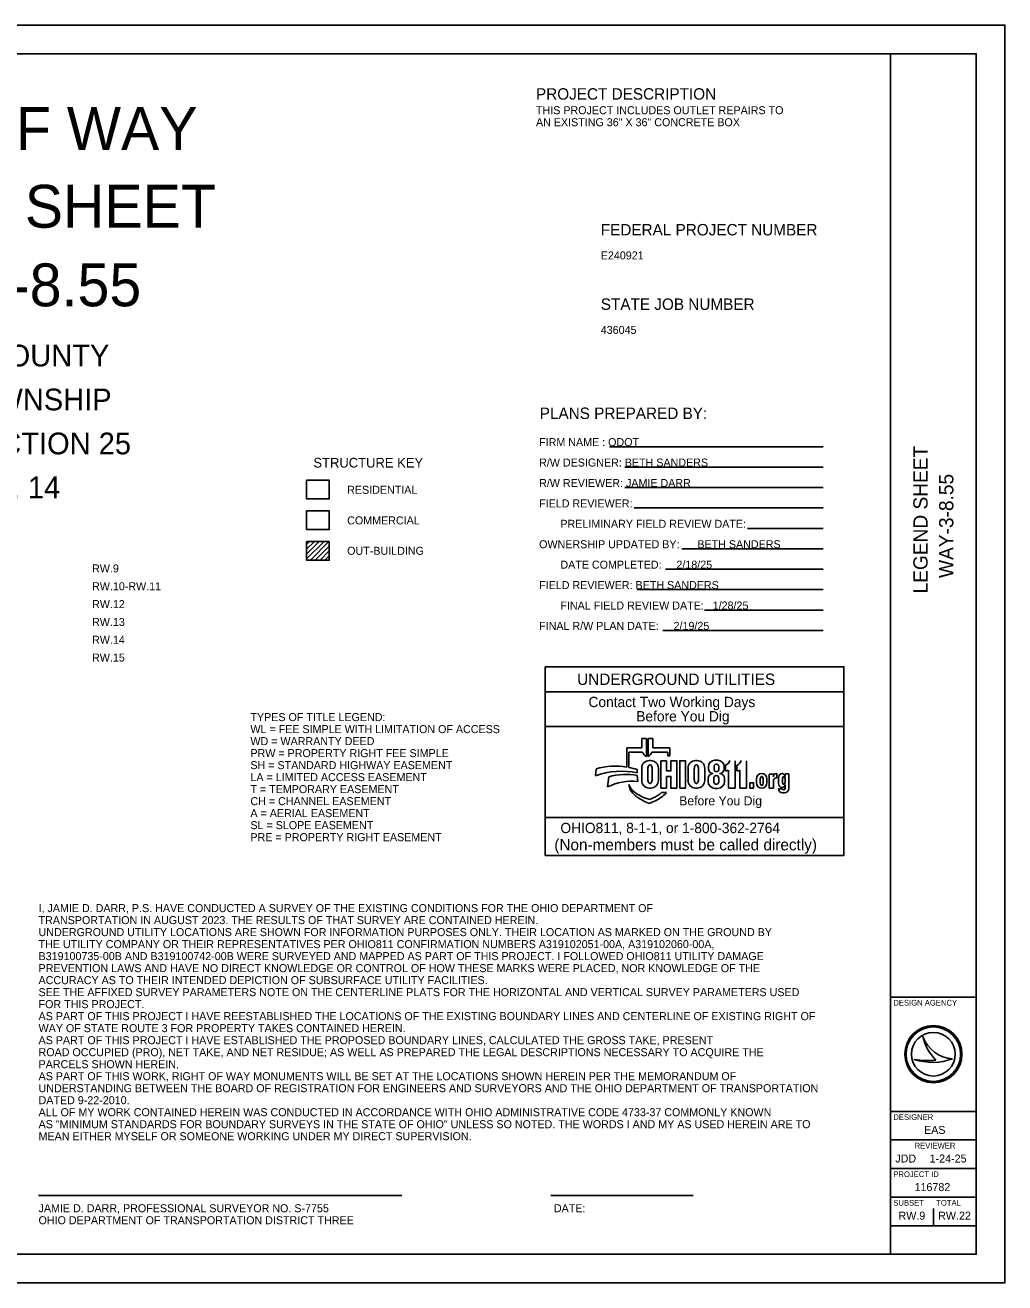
# Model space of a CAD drawing. Extents: x 0 to 34, y 0 to 22.
# Drawn here: x 16.87 to 34, y 0 to 22 of the extents above; entities that cross this region are included whole.
import ezdxf

# ---------------------------------------------------------------- set-up
doc = ezdxf.new("R2010")
doc.units = 0
for name, color, linetype in [('Default', 7, 'Continuous'), ('SC_Shading1', 7, 'Continuous'), ('SH_Border', 7, 'Continuous'), ('SH_Cut_Line', 7, 'Continuous'), ('SH_Data', 7, 'Continuous'), ('SH_Text', 7, 'Continuous')]:
    doc.layers.add(name, color=color, linetype=linetype)

msp = doc.modelspace()

# ---------------------------------------------------------------- linework, layer by layer
at = {"layer": 'Default'}
for p, q in [((17.102, 1.525), (23.455, 1.525)), ((26.062, 1.525), (28.549, 1.525))]:
    msp.add_line(p, q, dxfattribs=at)
at = {"layer": 'SC_Shading1'}
msp.add_lwpolyline([(21.79, 13.177), (22.187, 13.177), (22.187, 13.502), (21.79, 13.502)], close=True, dxfattribs=at)
at = {"layer": 'SH_Border'}
for p, q in [((32, 0.5), (32, 21.5)), ((32, 5), (33.5, 5)), ((32, 3), (33.5, 3)), ((32, 2.5), (33.5, 2.5)), ((32, 2), (33.5, 2)), ((32, 1.5), (33.5, 1.5)), ((32, 1), (33.5, 1))]:
    msp.add_line(p, q, dxfattribs=at)
msp.add_lwpolyline([(1.5, 21.5), (33.5, 21.5), (33.5, 0.5), (1.5, 0.5)], close=True, dxfattribs=at)
at = {"layer": 'SH_Cut_Line'}
msp.add_lwpolyline([(0, 0), (34, 0), (34, 22), (0, 22)], close=True, dxfattribs=at)
at = {"layer": 'SH_Data'}
for p, q in [((27.731, 9.524), (27.651, 9.524)), ((27.651, 9.524), (27.651, 9.357)), ((27.731, 9.207), (27.731, 9.524)), ((27.842, 9.524), (27.762, 9.524)), ((27.762, 9.524), (27.762, 9.207)), ((27.842, 9.357), (27.842, 9.524)), ((27.651, 9.357), (27.388, 9.357)), ((27.388, 9.357), (27.388, 9.023)), ((27.425, 9.016), (27.425, 9.28)), ((27.425, 9.28), (27.666, 9.28)), ((27.826, 9.28), (28.105, 9.28)), ((28.14, 9.357), (27.842, 9.357)), ((28.105, 9.28), (28.105, 9.217)), ((28.14, 9.217), (28.14, 9.357)), ((27.807, 9.136), (27.783, 9.136)), ((28.085, 9.134), (27.984, 9.134)), ((27.984, 9.134), (27.984, 8.656)), ((28.105, 9.217), (28.14, 9.217)), ((28.618, 9.136), (28.593, 9.136)), ((28.816, 9.028), (28.816, 8.992)), ((28.915, 8.975), (28.915, 9.034)), ((28.979, 9.142), (28.93, 9.142)), ((28.996, 9.034), (28.996, 8.975)), ((29.093, 8.992), (29.093, 9.028)), ((29.116, 8.954), (29.116, 9.056)), ((29.283, 9.134), (29.283, 8.656)), ((29.316, 8.954), (29.316, 9.056)), ((29.483, 9.134), (29.483, 8.656)), ((26.853, 8.988), (26.839, 8.872)), ((27.073, 8.853), (27.051, 8.674)), ((27.572, 8.921), (27.572, 8.979)), ((27.582, 8.77), (27.572, 8.876)), ((27.649, 9.002), (27.649, 8.79)), ((27.758, 8.807), (27.758, 8.99)), ((27.832, 8.99), (27.832, 8.807)), ((27.941, 8.79), (27.941, 9.002)), ((28.085, 8.656), (28.085, 8.859)), ((28.46, 9.002), (28.46, 8.79)), ((28.569, 8.807), (28.569, 8.99)), ((28.643, 8.99), (28.643, 8.807)), ((28.752, 8.79), (28.752, 9.002)), ((28.811, 8.822), (28.811, 8.771)), ((28.912, 8.762), (28.912, 8.823)), ((28.997, 8.823), (28.997, 8.762)), ((29.099, 8.771), (29.099, 8.822)), ((29.165, 8.656), (29.165, 8.968)), ((29.365, 8.656), (29.365, 8.968)), ((29.657, 8.747), (29.657, 8.815)), ((29.724, 8.746), (29.724, 8.815)), ((29.772, 8.815), (29.772, 8.746)), ((29.839, 8.815), (29.839, 8.747)), ((29.952, 8.9), (29.879, 8.9)), ((29.879, 8.9), (29.879, 8.656)), ((29.952, 8.853), (29.952, 8.9)), ((30.001, 8.833), (30.013, 8.833)), ((30.013, 8.908), (30.007, 8.908)), ((30.013, 8.833), (30.013, 8.908)), ((30.041, 8.735), (30.041, 8.839)), ((30.113, 8.749), (30.113, 8.825)), ((30.156, 8.855), (30.156, 8.901)), ((30.156, 8.901), (30.221, 8.901)), ((30.156, 8.825), (30.156, 8.749)), ((30.221, 8.901), (30.221, 8.643)), ((27.424, 8.717), (27.429, 8.69)), ((27.783, 8.656), (27.807, 8.656)), ((27.984, 8.656), (28.085, 8.656)), ((28.593, 8.656), (28.618, 8.656)), ((28.932, 8.65), (28.978, 8.65)), ((29.283, 8.656), (29.165, 8.656)), ((29.483, 8.656), (29.365, 8.656)), ((29.879, 8.656), (29.952, 8.656)), ((29.952, 8.656), (29.952, 8.784)), ((30.041, 8.643), (30.113, 8.643)), ((30.156, 8.643), (30.156, 8.712)), ((27.789, 8.456), (27.701, 8.486)), ((27.725, 8.41), (27.78, 8.385)), ((27.78, 8.385), (27.875, 8.426)), ((27.851, 8.482), (27.789, 8.456)), ((28.083, 8.576), (27.997, 8.576)), ((28.08, 8.574), (28.083, 8.576)), ((30.151, 8.573), (30.111, 8.573)), ((31.187, 7.478), (25.962, 7.478)), ((32.567, 4.31), (32.567, 4.31)), ((32.75, 4), (32.75, 4)), ((32.417, 3.91), (32.417, 3.91)), ((33.087, 3.919), (33.087, 3.919)), ((32.75, 1), (32.75, 1.3))]:
    msp.add_line(p, q, dxfattribs=at)
for points in [[(25.962, 10.778), (31.187, 10.778), (31.187, 10.338), (25.962, 10.338)], [(25.962, 10.338), (31.187, 10.338), (31.187, 9.733), (25.962, 9.733)], [(25.962, 9.733), (31.187, 9.733), (31.187, 8.138), (25.962, 8.138)], [(29.541, 8.746), (29.607, 8.746), (29.607, 8.656), (29.541, 8.656)], [(25.962, 8.138), (31.187, 8.138), (31.187, 7.478), (25.962, 7.478)]]:
    msp.add_lwpolyline(points, close=True, dxfattribs=at)
for points in [[(28.085, 8.859), (28.161, 8.859), (28.161, 8.656), (28.263, 8.656), (28.263, 9.134), (28.161, 9.134), (28.161, 8.954), (28.085, 8.954), (28.085, 9.134)], [(28.314, 8.656), (28.416, 8.656), (28.416, 9.134), (28.314, 9.134), (28.314, 8.656)], [(28.897, 8.909), (28.897, 8.908)], [(29.013, 8.908), (29.013, 8.909)]]:
    msp.add_lwpolyline(points, dxfattribs=at)
for radius in [0.5, 0.477, 0.477, 0.382]:
    msp.add_circle((32.75, 4), radius, dxfattribs=at)
for centre, radius, start, end in [((27.803, 9.335), 0.147, 201.9296, 240.7469), ((27.69, 9.335), 0.147, 299.2531, 338.0704), ((27.196, 7.814), 1.224, 81.0007, 106.3144), ((27.783, 9.002), 0.134, 90, 180), ((27.807, 9.002), 0.134, 0, 90), ((28.593, 9.002), 0.134, 90, 180), ((28.618, 9.002), 0.134, 0, 90), ((28.93, 9.028), 0.114, 90, 180), ((28.979, 9.028), 0.114, 0, 90), ((29.066, 9.178), 0.132, 292.5572, 340.7355), ((29.266, 9.178), 0.132, 292.5572, 340.7355), ((27.291, 7.618), 1.332, 77.8238, 109.8274), ((27.372, 7.801), 1.094, 79.44, 105.8467), ((27.196, 7.814), 1.224, 72.1402, 79.2074), ((28.897, 8.822), 0.0865, 90, 180), ((28.9, 8.992), 0.0837, 180, 268.1442), ((29.01, 8.992), 0.0837, 272.2058, 0), ((29.013, 8.822), 0.0865, 0, 90), ((29.104, 9.086), 0.132, 275.1733, 297.0931), ((29.304, 9.086), 0.132, 275.1733, 297.0931), ((29.752, 8.815), 0.0956, 92.5886, 180), ((29.744, 8.815), 0.0956, 0, 87.4114), ((30.007, 8.853), 0.0548, 90, 180), ((30.001, 8.784), 0.0493, 90, 180), ((30.109, 8.839), 0.0686, 92.6865, 180), ((30.103, 8.855), 0.0524, 0, 86.9262), ((27.479, 7.826), 0.95, 83.8248, 116.8021), ((27.704, 8.824), 0.3, 201.0457, 232.5314), ((27.64, 8.726), 0.214, 189.6817, 216.0884), ((27.84, 8.871), 0.461, 216.0884, 235.7167), ((27.992, 9.2), 0.773, 232.5314, 241.794), ((27.783, 8.79), 0.134, 180, 270), ((27.807, 8.79), 0.134, 270, 0), ((28.593, 8.79), 0.134, 180, 270), ((28.618, 8.79), 0.134, 270, 0), ((28.932, 8.771), 0.121, 180, 270), ((28.978, 8.771), 0.121, 270, 0), ((29.752, 8.747), 0.0956, 180, 267.4114), ((29.744, 8.747), 0.0956, 272.5886, 0), ((30.11, 8.735), 0.0692, 180, 265.7132), ((30.111, 8.643), 0.0699, 180, 270), ((30.109, 8.712), 0.0467, 264.7825, 0), ((30.151, 8.643), 0.0699, 270, 0), ((28.088, 9.236), 0.903, 235.7167, 246.2325), ((27.865, 8.962), 0.504, 241.794, 250.9821), ((27.637, 8.976), 0.538, 293.4582, 312.0712), ((27.637, 8.976), 0.599, 293.4582, 317.8286), ((33.116, 4.498), 0.58, 198.9257, 198.9319), ((33.347, 4.47), 0.796, 191.6379, 191.6421), ((33.116, 4.498), 0.58, 198.9319, 267.1657), ((33.347, 4.47), 0.796, 191.6421, 226.0947), ((32.739, 4.87), 1.013, 251.4576, 290.0832), ((32.648, 5.154), 1.266, 259.4964, 259.4995), ((32.739, 4.87), 1.013, 251.4527, 251.4576), ((32.648, 5.154), 1.266, 259.4995, 276.6672)]:
    msp.add_arc(centre, radius, start, end, dxfattribs=at)
for centre, major_axis, ratio, start_param, end_param in [((27.795, 8.99), (0, 0.0723), 0.514403, 4.712389, 7.853982), ((28.606, 8.99), (0, 0.0723), 0.514403, 4.712389, 7.853982), ((28.956, 9.034), (0.0404, 0), 0.969373, 0, 3.141593), ((27.795, 8.807), (0, 0.0723), 0.514403, 1.570796, 4.712389), ((28.606, 8.807), (0, 0.0723), 0.514403, 1.570796, 4.712389), ((28.954, 8.823), (0, 0.0535), 0.794529, 4.712389, 7.853982), ((28.956, 8.975), (0.0404, 0), 0.818453, 3.141593, 6.283185), ((29.748, 8.815), (0, 0.0434), 0.553236, 4.712389, 7.853982), ((30.134, 8.825), (0, 0.0275), 0.777179, 4.712389, 7.853982), ((28.954, 8.762), (0.0425, 0), 0.959837, 3.141593, 6.283185), ((29.748, 8.746), (0, 0.046), 0.522014, 1.570796, 4.712389), ((30.134, 8.749), (0, 0.0275), 0.777179, 1.570796, 4.712389), ((30.134, 8.643), (0.0214, 0), 0.959012, 3.141593, 6.283185)]:
    msp.add_ellipse(centre, major_axis=major_axis, ratio=ratio, start_param=start_param, end_param=end_param, dxfattribs=at)
at = {"layer": 'SH_Text'}
for p, q in [((27.088, 14.626), (30.825, 14.626)), ((27.352, 14.269), (30.825, 14.269)), ((27.352, 13.912), (30.825, 13.912)), ((27.516, 13.554), (30.825, 13.554)), ((29.497, 13.197), (30.825, 13.197)), ((21.79, 12.966), (21.792, 12.967)), ((21.79, 12.916), (21.842, 12.967)), ((21.79, 12.831), (21.927, 12.967)), ((21.79, 12.746), (22.011, 12.967)), ((21.79, 12.662), (22.096, 12.967)), ((21.855, 12.641), (22.181, 12.967)), ((21.939, 12.641), (22.187, 12.889)), ((22.024, 12.641), (22.187, 12.805)), ((28.352, 12.84), (30.825, 12.84)), ((21.79, 12.646), (21.795, 12.641)), ((22.109, 12.641), (22.187, 12.72)), ((28.067, 12.483), (30.825, 12.483)), ((27.569, 12.126), (30.825, 12.126)), ((28.75, 11.768), (30.825, 11.768)), ((28.021, 11.412), (30.825, 11.412))]:
    msp.add_line(p, q, dxfattribs=at)
for points in [[(21.79, 14.038), (22.187, 14.038), (22.187, 13.712), (21.79, 13.712)], [(21.79, 12.967), (22.187, 12.967), (22.187, 12.641), (21.79, 12.641)]]:
    msp.add_lwpolyline(points, close=True, dxfattribs=at)

# ---------------------------------------------------------------- texts
at = {"layer": 'Default'}
for s, p in [('I, JAMIE D. DARR, P.S. HAVE CONDUCTED A SURVEY OF THE EXISTING CONDITIONS FOR THE OHIO DEPARTMENT OF', (17.102, 6.485)), ('TRANSPORTATION IN AUGUST 2023. THE RESULTS OF THAT SURVEY ARE CONTAINED HEREIN.', (17.102, 6.275)), ('UNDERGROUND UTILITY LOCATIONS ARE SHOWN FOR INFORMATION PURPOSES ONLY. THEIR LOCATION AS MARKED ON THE GROUND BY ', (17.102, 6.065)), ('THE UTILITY COMPANY OR THEIR REPRESENTATIVES PER OHIO811 CONFIRMATION NUMBERS A319102051-00A, A319102060-00A,', (17.102, 5.855)), ('B319100735-00B AND B319100742-00B WERE SURVEYED AND MAPPED AS PART OF THIS PROJECT. I FOLLOWED OHIO811 UTILITY DAMAGE', (17.102, 5.645)), ('PREVENTION LAWS AND HAVE NO DIRECT KNOWLEDGE OR CONTROL OF HOW THESE MARKS WERE PLACED, NOR KNOWLEDGE OF THE ', (17.102, 5.435)), ('ACCURACY AS TO THEIR INTENDED DEPICTION OF SUBSURFACE UTILITY FACILITIES.', (17.102, 5.225)), ('SEE THE AFFIXED SURVEY PARAMETERS NOTE ON THE CENTERLINE PLATS FOR THE HORIZONTAL AND VERTICAL SURVEY PARAMETERS USED ', (17.102, 5.015)), ('FOR THIS PROJECT.', (17.102, 4.805)), ('AS PART OF THIS PROJECT I HAVE REESTABLISHED THE LOCATIONS OF THE EXISTING BOUNDARY LINES AND CENTERLINE OF EXISTING RIGHT OF ', (17.102, 4.595)), ('WAY OF STATE ROUTE 3 FOR PROPERTY TAKES CONTAINED HEREIN.', (17.102, 4.385)), ('AS PART OF THIS PROJECT I HAVE ESTABLISHED THE PROPOSED BOUNDARY LINES, CALCULATED THE GROSS TAKE, PRESENT', (17.102, 4.175)), ('ROAD OCCUPIED (PRO), NET TAKE, AND NET RESIDUE; AS WELL AS PREPARED THE LEGAL DESCRIPTIONS NECESSARY TO ACQUIRE THE', (17.102, 3.965)), ('PARCELS SHOWN HEREIN.', (17.102, 3.755)), ('AS PART OF THIS WORK, RIGHT OF WAY MONUMENTS WILL BE SET AT THE LOCATIONS SHOWN HEREIN PER THE MEMORANDUM OF ', (17.102, 3.545)), ('UNDERSTANDING BETWEEN THE BOARD OF REGISTRATION FOR ENGINEERS AND SURVEYORS AND THE OHIO DEPARTMENT OF TRANSPORTATION ', (17.102, 3.335)), ('DATED 9-22-2010.', (17.102, 3.125)), ('ALL OF MY WORK CONTAINED HEREIN WAS CONDUCTED IN ACCORDANCE WITH OHIO ADMINISTRATIVE CODE 4733-37 COMMONLY KNOWN', (17.102, 2.915)), ('AS "MINIMUM STANDARDS FOR BOUNDARY SURVEYS IN THE STATE OF OHIO" UNLESS SO NOTED. THE WORDS I AND MY AS USED HEREIN ARE TO', (17.102, 2.705)), ('MEAN EITHER MYSELF OR SOMEONE WORKING UNDER MY DIRECT SUPERVISION.', (17.102, 2.495)), ('JAMIE D. DARR, PROFESSIONAL SURVEYOR NO. S-7755                                                               ', (17.102, 1.235)), (' DATE:', (26.062, 1.235)), ('OHIO DEPARTMENT OF TRANSPORTATION DISTRICT THREE', (17.102, 1.025))]:
    msp.add_text(s, height=0.14, dxfattribs=at).set_placement(p)
at = {"layer": 'SH_Data'}
for s, height, p in [('RIGHT OF WAY', 0.75, (12.527, 19.816)), ('LEGEND SHEET', 0.75, (12.458, 18.457)), ('  WAY-3-8.55 ', 0.75, (12.879, 17.082)), ('      WAYNE COUNTY     ', 0.38, (13.343, 16.03)), ('     PLAIN TOWNSHIP    ', 0.38, (13.326, 15.262)), ('   NE QTR SECTION 25   ', 0.38, (13.27, 14.493)), ('      T. 19, R. 14     ', 0.38, (13.979, 13.725)), ('RW.9  ', 0.14, (18.038, 12.427)), ('RW.10-RW.11', 0.14, (18.038, 12.115)), ('RW.12 ', 0.14, (18.038, 11.803)), ('RW.13 ', 0.14, (18.038, 11.491)), ('RW.14 ', 0.14, (18.038, 11.179)), ('RW.15 ', 0.14, (18.038, 10.867)), ('UNDERGROUND UTILITIES', 0.2, (26.521, 10.458)), ('Contact Two Working Days', 0.18, (26.719, 10.071)), ('Before You Dig', 0.18, (27.554, 9.821)), ('Before You Dig', 0.15972, (28.305, 8.353)), ('OHIO811, 8-1-1, or 1-800-362-2764', 0.18, (26.228, 7.867)), ('(Non-members must be called directly)', 0.2, (26.122, 7.565)), ('DESIGN AGENCY', 0.1, (32.05, 4.85)), ('DESIGNER', 0.1, (32.05, 2.85)), ('EAS', 0.14, (32.587, 2.605)), ('REVIEWER', 0.1, (32.422, 2.35)), ('JDD', 0.14, (32.084, 2.105)), ('1-24-25', 0.14, (32.685, 2.105)), ('PROJECT ID', 0.1, (32.05, 1.85)), ('116782', 0.14, (32.421, 1.605)), ('SUBSET', 0.1, (32.05, 1.35)), ('TOTAL', 0.1, (32.8, 1.35)), ('RW.9', 0.14, (32.14, 1.105)), ('RW.22', 0.14, (32.834, 1.105))]:
    msp.add_text(s, height=height, dxfattribs=at).set_placement(p)
for s, p in [('LEGEND SHEET', (32.65, 12.06)), ('WAY-3-8.55', (33.1, 12.33))]:
    msp.add_text(s, height=0.25, rotation=90, dxfattribs=at).set_placement(p)
at = {"layer": 'SH_Text'}
for s, height, p in [('PROJECT DESCRIPTION', 0.2, (25.801, 20.697)), ('THIS PROJECT INCLUDES OUTLET REPAIRS TO', 0.14, (25.801, 20.442)), ('AN EXISTING 36" X 36" CONCRETE BOX', 0.14, (25.801, 20.232)), ('FEDERAL PROJECT NUMBER', 0.2, (26.934, 18.322)), ('E240921   ', 0.14, (26.934, 17.902)), ('STATE JOB NUMBER', 0.2, (26.934, 17.019)), ('436045    ', 0.14, (26.934, 16.599)), ('PLANS PREPARED BY:', 0.2, (25.867, 15.111)), ('FIRM NAME : ODOT', 0.14, (25.856, 14.636)), ('STRUCTURE KEY', 0.17, (21.908, 14.261)), ('R/W DESIGNER: BETH SANDERS', 0.14, (25.856, 14.279)), ('RESIDENTIAL', 0.14, (22.499, 13.802)), ('R/W REVIEWER: JAMIE DARR', 0.14, (25.856, 13.921)), ('FIELD REVIEWER:', 0.14, (25.856, 13.564)), ('COMMERCIAL', 0.14, (22.499, 13.267)), ('PRELIMINARY FIELD REVIEW DATE:', 0.14, (26.228, 13.207)), ('OWNERSHIP UPDATED BY:      BETH SANDERS', 0.14, (25.856, 12.85)), ('OUT-BUILDING', 0.14, (22.499, 12.735)), ('DATE COMPLETED:     2/18/25', 0.14, (26.228, 12.493)), ('FIELD REVIEWER: BETH SANDERS', 0.14, (25.856, 12.136)), ('FINAL FIELD REVIEW DATE:   1/28/25', 0.14, (26.228, 11.778)), ('FINAL R/W PLAN DATE:     2/19/25', 0.14, (25.856, 11.422)), ('TYPES OF TITLE LEGEND:', 0.14, (20.807, 9.826)), ('WL = FEE SIMPLE WITH LIMITATION OF ACCESS', 0.14, (20.807, 9.616)), ('WD = WARRANTY DEED', 0.14, (20.807, 9.406)), ('PRW = PROPERTY RIGHT FEE SIMPLE', 0.14, (20.807, 9.196)), ('SH = STANDARD HIGHWAY EASEMENT', 0.14, (20.807, 8.986)), ('LA = LIMITED ACCESS EASEMENT', 0.14, (20.807, 8.776)), ('T = TEMPORARY EASEMENT', 0.14, (20.807, 8.566)), ('CH = CHANNEL EASEMENT', 0.14, (20.807, 8.356)), ('A = AERIAL EASEMENT', 0.14, (20.807, 8.146)), ('SL = SLOPE EASEMENT', 0.14, (20.807, 7.936)), ('PRE = PROPERTY RIGHT EASEMENT', 0.14, (20.807, 7.726))]:
    msp.add_text(s, height=height, dxfattribs=at).set_placement(p)

doc.saveas('drawing.dxf')
